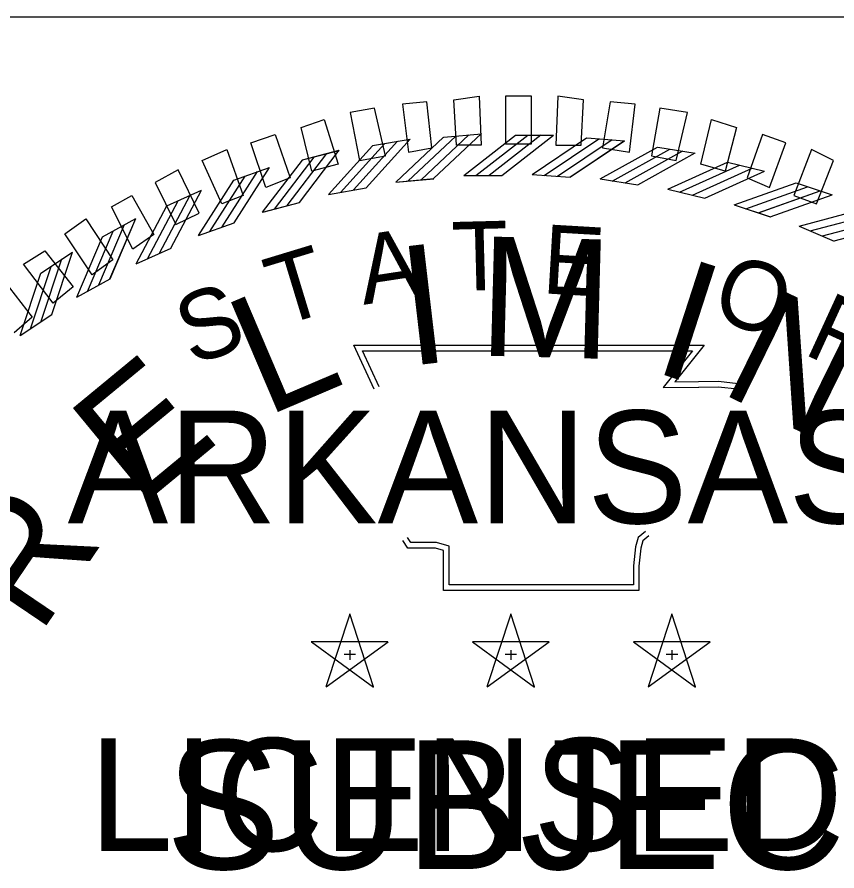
# Model space of a CAD drawing. Extents: x 16 to 1228740, y 11 to 152440.
# Drawn here: x 17.7163 to 17.7977, y 10.9139 to 10.9986 of the extents above; entities that cross this region are included whole.
import ezdxf

# ---------------------------------------------------------------- set-up
doc = ezdxf.new("R2010")
doc.units = 0
for name, color, linetype in [('B_StampERBB', 7, 'Continuous'), ('R_No Plot', 7, 'Continuous'), ('STAMP_FRED', 7, 'Continuous'), ('STAMP_JUSTIN', 7, 'Continuous'), ('STAMP_PRELIM', 7, 'Continuous')]:
    doc.layers.add(name, color=color, linetype=linetype)

msp = doc.modelspace()

# ---------------------------------------------------------------- linework, layer by layer
at = {"layer": 'B_StampERBB'}
for p, q in [((17.751633, 10.985868), (17.755345, 10.986523)), ((17.758689, 10.986711), (17.762443, 10.987057)), ((17.765828, 10.986922), (17.769598, 10.986922)), ((17.77289, 10.986639), (17.776649, 10.986362)), ((17.779937, 10.985724), (17.783661, 10.985138)), ((17.74467, 10.984445), (17.748316, 10.985404)), ((17.786885, 10.98423), (17.790548, 10.983338)), ((17.737849, 10.982452), (17.741403, 10.983709)), ((17.767464, 10.983016), (17.771233, 10.982738)), ((17.753934, 10.982244), (17.757697, 10.982591)), ((17.760683, 10.98291), (17.764462, 10.98291)), ((17.774231, 10.982561), (17.777964, 10.981973)), ((17.793685, 10.982168), (17.797262, 10.980976)), ((17.731215, 10.979903), (17.734654, 10.981449)), ((17.747263, 10.981024), (17.750984, 10.98168)), ((17.780937, 10.981549), (17.784609, 10.980655)), ((17.740715, 10.979257), (17.74437, 10.980218)), ((17.787537, 10.979987), (17.791122, 10.978793)), ((17.724815, 10.976814), (17.728114, 10.978639)), ((17.734336, 10.976955), (17.737898, 10.978215)), ((17.793985, 10.977885), (17.797459, 10.976399)), ((17.718692, 10.973208), (17.721829, 10.975299)), ((17.728168, 10.974134), (17.731615, 10.975684)), ((17.722255, 10.970814), (17.725562, 10.972643)), ((17.716636, 10.967016), (17.71978, 10.969112)), ((17.749354, 10.939355), (17.746995, 10.932119)), ((17.751704, 10.932123), (17.749359, 10.939363)), ((17.765345, 10.939355), (17.762986, 10.932119)), ((17.767695, 10.932123), (17.76535, 10.939363)), ((17.781336, 10.939355), (17.778977, 10.932119)), ((17.783686, 10.932123), (17.781341, 10.939363)), ((17.753156, 10.936593), (17.745545, 10.9366)), ((17.745552, 10.936593), (17.751705, 10.932113)), ((17.747004, 10.932123), (17.753165, 10.936591)), ((17.769147, 10.936593), (17.761536, 10.9366)), ((17.761543, 10.936593), (17.767696, 10.932113)), ((17.762995, 10.932123), (17.769157, 10.936591)), ((17.785138, 10.936593), (17.777527, 10.9366)), ((17.777534, 10.936593), (17.783687, 10.932113)), ((17.778986, 10.932123), (17.785148, 10.936591)), ((17.749361, 10.935783), (17.749361, 10.934828)), ((17.765352, 10.935783), (17.765352, 10.934828)), ((17.781343, 10.935783), (17.781343, 10.934828)), ((17.748812, 10.935377), (17.749943, 10.935377)), ((17.764803, 10.935377), (17.765934, 10.935377)), ((17.780794, 10.935377), (17.781926, 10.935377))]:
    msp.add_line(p, q, dxfattribs=at)
for points in [[(17.749741, 10.981475), (17.754109, 10.986319)], [(17.750979, 10.981682), (17.755348, 10.986526)], [(17.75393, 10.982241), (17.758684, 10.986707)], [(17.755139, 10.982341), (17.759893, 10.986807)], [(17.756441, 10.98249), (17.761195, 10.986956)], [(17.757692, 10.982593), (17.762446, 10.98706)], [(17.760679, 10.982906), (17.765823, 10.986918)], [(17.761892, 10.982895), (17.767036, 10.986907)], [(17.763202, 10.982924), (17.768346, 10.986936)], [(17.764458, 10.982913), (17.769601, 10.986924)], [(17.76746, 10.983012), (17.772884, 10.986636)], [(17.768669, 10.982912), (17.774093, 10.986535)], [(17.769977, 10.982845), (17.775401, 10.986468)], [(17.771229, 10.982741), (17.776653, 10.986365)], [(17.747259, 10.98102), (17.751628, 10.985864)], [(17.748456, 10.98122), (17.752825, 10.986064)], [(17.774226, 10.982558), (17.779931, 10.985721)], [(17.775423, 10.982358), (17.781128, 10.985521)], [(17.741888, 10.97955), (17.745842, 10.984738)], [(17.743147, 10.979911), (17.747101, 10.9851)], [(17.744365, 10.98022), (17.748319, 10.985408)], [(17.776721, 10.982183), (17.782426, 10.985346)], [(17.77796, 10.981977), (17.783665, 10.98514)], [(17.740712, 10.979252), (17.744666, 10.984441)], [(17.780932, 10.981547), (17.786879, 10.984228)], [(17.782108, 10.981249), (17.788055, 10.98393)], [(17.736705, 10.977808), (17.740218, 10.983305)], [(17.737893, 10.978216), (17.741405, 10.983713)], [(17.783387, 10.980967), (17.789334, 10.983648)], [(17.784605, 10.980659), (17.790552, 10.98334)], [(17.734333, 10.97695), (17.737845, 10.982447)], [(17.73548, 10.977344), (17.738993, 10.982841)], [(17.787531, 10.979985), (17.793679, 10.982166)], [(17.73161, 10.975685), (17.734656, 10.981453)], [(17.788679, 10.979591), (17.794827, 10.981772)], [(17.789931, 10.979205), (17.796078, 10.981386)], [(17.729277, 10.974617), (17.732323, 10.980385)], [(17.730459, 10.97518), (17.733506, 10.980948)], [(17.791118, 10.978797), (17.797266, 10.980978)], [(17.728166, 10.974129), (17.731212, 10.979898)], [(17.793979, 10.977884), (17.800286, 10.979549)], [(17.79509, 10.977396), (17.801397, 10.979062)], [(17.724452, 10.972045), (17.727011, 10.978045)], [(17.725556, 10.972643), (17.728116, 10.978643)], [(17.796306, 10.976908), (17.802613, 10.978574)], [(17.797456, 10.976403), (17.803763, 10.978069)], [(17.72332, 10.971386), (17.725879, 10.977386)], [(17.722253, 10.970809), (17.724812, 10.976809)], [(17.719775, 10.969112), (17.72183, 10.975303)], [(17.718724, 10.968425), (17.720779, 10.974616)], [(17.71765, 10.967675), (17.719705, 10.973866)], [(17.716634, 10.967011), (17.718689, 10.973202)], [(17.751782, 10.96169), (17.749773, 10.966041), (17.784542, 10.966062), (17.781637, 10.962412), (17.783999, 10.962442), (17.785972, 10.962468), (17.787944, 10.962253)], [(17.752282, 10.96192), (17.750633, 10.965491), (17.7834, 10.96551), (17.780483, 10.961846), (17.784006, 10.961892), (17.785946, 10.961917), (17.787884, 10.961706)], [(17.778715, 10.947546), (17.777986, 10.946952), (17.777731, 10.946018), (17.777526, 10.944143), (17.777526, 10.94226), (17.759218, 10.94226), (17.759218, 10.944954), (17.759218, 10.946083), (17.757962, 10.946466), (17.755417, 10.946466), (17.755089, 10.946966)], [(17.779063, 10.947119), (17.77847, 10.946636), (17.778273, 10.945915), (17.778077, 10.944113), (17.778077, 10.941709), (17.758667, 10.941709), (17.758667, 10.944954), (17.758667, 10.945675), (17.75788, 10.945915), (17.755119, 10.945915), (17.754629, 10.946664)]]:
    msp.add_lwpolyline(points, dxfattribs=at)
at = {"layer": 'R_No Plot'}
msp.add_line((17.887998, 10.998635), (17.47349, 10.998635), dxfattribs=at)
at = {"layer": 'STAMP_FRED'}
for p, q in [((17.751633, 10.985868), (17.755345, 10.986523)), ((17.758689, 10.986711), (17.762443, 10.987057)), ((17.765828, 10.986922), (17.769598, 10.986922)), ((17.77289, 10.986639), (17.776649, 10.986362)), ((17.779937, 10.985724), (17.783661, 10.985138)), ((17.74467, 10.984445), (17.748316, 10.985404)), ((17.786885, 10.98423), (17.790548, 10.983338)), ((17.737849, 10.982452), (17.741403, 10.983709)), ((17.767464, 10.983016), (17.771233, 10.982738)), ((17.753934, 10.982244), (17.757697, 10.982591)), ((17.760683, 10.98291), (17.764462, 10.98291)), ((17.774231, 10.982561), (17.777964, 10.981973)), ((17.793685, 10.982168), (17.797262, 10.980976)), ((17.731215, 10.979903), (17.734654, 10.981449)), ((17.747263, 10.981024), (17.750984, 10.98168)), ((17.780937, 10.981549), (17.784609, 10.980655)), ((17.740715, 10.979257), (17.74437, 10.980218)), ((17.787537, 10.979987), (17.791122, 10.978793)), ((17.724815, 10.976814), (17.728114, 10.978639)), ((17.734336, 10.976955), (17.737898, 10.978215)), ((17.793985, 10.977885), (17.797459, 10.976399)), ((17.718692, 10.973208), (17.721829, 10.975299)), ((17.728168, 10.974134), (17.731615, 10.975684)), ((17.722255, 10.970814), (17.725562, 10.972643)), ((17.716636, 10.967016), (17.71978, 10.969112)), ((17.749354, 10.939355), (17.746995, 10.932119)), ((17.751704, 10.932123), (17.749359, 10.939363)), ((17.765345, 10.939355), (17.762986, 10.932119)), ((17.767695, 10.932123), (17.76535, 10.939363)), ((17.781336, 10.939355), (17.778977, 10.932119)), ((17.783686, 10.932123), (17.781341, 10.939363)), ((17.753156, 10.936593), (17.745545, 10.9366)), ((17.745552, 10.936593), (17.751705, 10.932113)), ((17.747004, 10.932123), (17.753165, 10.936591)), ((17.769147, 10.936593), (17.761536, 10.9366)), ((17.761543, 10.936593), (17.767696, 10.932113)), ((17.762995, 10.932123), (17.769157, 10.936591)), ((17.785138, 10.936593), (17.777527, 10.9366)), ((17.777534, 10.936593), (17.783687, 10.932113)), ((17.778986, 10.932123), (17.785148, 10.936591)), ((17.749361, 10.935783), (17.749361, 10.934828)), ((17.765352, 10.935783), (17.765352, 10.934828)), ((17.781343, 10.935783), (17.781343, 10.934828)), ((17.748812, 10.935377), (17.749943, 10.935377)), ((17.764803, 10.935377), (17.765934, 10.935377)), ((17.780794, 10.935377), (17.781926, 10.935377))]:
    msp.add_line(p, q, dxfattribs=at)
for points in [[(17.749741, 10.981475), (17.754109, 10.986319)], [(17.750979, 10.981682), (17.755348, 10.986526)], [(17.75393, 10.982241), (17.758684, 10.986707)], [(17.755139, 10.982341), (17.759893, 10.986807)], [(17.756441, 10.98249), (17.761195, 10.986956)], [(17.757692, 10.982593), (17.762446, 10.98706)], [(17.760679, 10.982906), (17.765823, 10.986918)], [(17.761892, 10.982895), (17.767036, 10.986907)], [(17.763202, 10.982924), (17.768346, 10.986936)], [(17.764458, 10.982913), (17.769601, 10.986924)], [(17.76746, 10.983012), (17.772884, 10.986636)], [(17.768669, 10.982912), (17.774093, 10.986535)], [(17.769977, 10.982845), (17.775401, 10.986468)], [(17.771229, 10.982741), (17.776653, 10.986365)], [(17.747259, 10.98102), (17.751628, 10.985864)], [(17.748456, 10.98122), (17.752825, 10.986064)], [(17.774226, 10.982558), (17.779931, 10.985721)], [(17.775423, 10.982358), (17.781128, 10.985521)], [(17.741888, 10.97955), (17.745842, 10.984738)], [(17.743147, 10.979911), (17.747101, 10.9851)], [(17.744365, 10.98022), (17.748319, 10.985408)], [(17.776721, 10.982183), (17.782426, 10.985346)], [(17.77796, 10.981977), (17.783665, 10.98514)], [(17.740712, 10.979252), (17.744666, 10.984441)], [(17.780932, 10.981547), (17.786879, 10.984228)], [(17.782108, 10.981249), (17.788055, 10.98393)], [(17.736705, 10.977808), (17.740218, 10.983305)], [(17.737893, 10.978216), (17.741405, 10.983713)], [(17.783387, 10.980967), (17.789334, 10.983648)], [(17.784605, 10.980659), (17.790552, 10.98334)], [(17.734333, 10.97695), (17.737845, 10.982447)], [(17.73548, 10.977344), (17.738993, 10.982841)], [(17.787531, 10.979985), (17.793679, 10.982166)], [(17.73161, 10.975685), (17.734656, 10.981453)], [(17.788679, 10.979591), (17.794827, 10.981772)], [(17.789931, 10.979205), (17.796078, 10.981386)], [(17.729277, 10.974617), (17.732323, 10.980385)], [(17.730459, 10.97518), (17.733506, 10.980948)], [(17.791118, 10.978797), (17.797266, 10.980978)], [(17.728166, 10.974129), (17.731212, 10.979898)], [(17.793979, 10.977884), (17.800286, 10.979549)], [(17.79509, 10.977396), (17.801397, 10.979062)], [(17.724452, 10.972045), (17.727011, 10.978045)], [(17.725556, 10.972643), (17.728116, 10.978643)], [(17.796306, 10.976908), (17.802613, 10.978574)], [(17.797456, 10.976403), (17.803763, 10.978069)], [(17.72332, 10.971386), (17.725879, 10.977386)], [(17.722253, 10.970809), (17.724812, 10.976809)], [(17.719775, 10.969112), (17.72183, 10.975303)], [(17.718724, 10.968425), (17.720779, 10.974616)], [(17.71765, 10.967675), (17.719705, 10.973866)], [(17.716634, 10.967011), (17.718689, 10.973202)], [(17.751782, 10.96169), (17.749773, 10.966041), (17.784542, 10.966062), (17.781637, 10.962412), (17.783999, 10.962442), (17.785972, 10.962468), (17.787944, 10.962253)], [(17.752282, 10.96192), (17.750633, 10.965491), (17.7834, 10.96551), (17.780483, 10.961846), (17.784006, 10.961892), (17.785946, 10.961917), (17.787884, 10.961706)], [(17.778715, 10.947546), (17.777986, 10.946952), (17.777731, 10.946018), (17.777526, 10.944143), (17.777526, 10.94226), (17.759218, 10.94226), (17.759218, 10.944954), (17.759218, 10.946083), (17.757962, 10.946466), (17.755417, 10.946466), (17.755089, 10.946966)], [(17.779063, 10.947119), (17.77847, 10.946636), (17.778273, 10.945915), (17.778077, 10.944113), (17.778077, 10.941709), (17.758667, 10.941709), (17.758667, 10.944954), (17.758667, 10.945675), (17.75788, 10.945915), (17.755119, 10.945915), (17.754629, 10.946664)]]:
    msp.add_lwpolyline(points, dxfattribs=at)
at = {"layer": 'STAMP_JUSTIN'}
for p, q in [((17.751633, 10.985867), (17.755345, 10.986522)), ((17.758689, 10.98671), (17.762443, 10.987056)), ((17.765828, 10.98692), (17.769598, 10.98692)), ((17.772889, 10.986638), (17.776649, 10.986361)), ((17.779937, 10.985723), (17.783661, 10.985137)), ((17.74467, 10.984444), (17.748316, 10.985403)), ((17.786884, 10.984229), (17.790547, 10.983337)), ((17.737849, 10.982451), (17.741403, 10.983708)), ((17.767464, 10.983015), (17.771233, 10.982737)), ((17.753934, 10.982244), (17.757697, 10.98259)), ((17.760683, 10.982909), (17.764462, 10.982909)), ((17.774231, 10.98256), (17.777963, 10.981972)), ((17.793685, 10.982167), (17.797261, 10.980975)), ((17.731216, 10.979902), (17.734654, 10.981448)), ((17.747263, 10.981023), (17.750984, 10.981679)), ((17.780937, 10.981548), (17.784608, 10.980654)), ((17.740716, 10.979256), (17.74437, 10.980217)), ((17.787536, 10.979986), (17.791121, 10.978792)), ((17.724816, 10.976814), (17.728115, 10.978638)), ((17.734336, 10.976954), (17.737899, 10.978214)), ((17.793984, 10.977884), (17.797458, 10.976398)), ((17.718693, 10.973207), (17.72183, 10.975298)), ((17.728169, 10.974134), (17.731615, 10.975683)), ((17.722256, 10.970813), (17.725562, 10.972642)), ((17.716637, 10.967016), (17.719781, 10.969112)), ((17.749354, 10.939355), (17.746995, 10.932119)), ((17.751704, 10.932123), (17.749359, 10.939363)), ((17.765345, 10.939355), (17.762986, 10.932119)), ((17.767695, 10.932123), (17.76535, 10.939363)), ((17.781336, 10.939355), (17.778977, 10.932119)), ((17.783685, 10.932123), (17.78134, 10.939363)), ((17.753156, 10.936593), (17.745545, 10.9366)), ((17.745552, 10.936593), (17.751705, 10.932114)), ((17.747004, 10.932123), (17.753165, 10.936591)), ((17.769147, 10.936593), (17.761536, 10.9366)), ((17.761543, 10.936593), (17.767696, 10.932114)), ((17.762995, 10.932123), (17.769156, 10.936591)), ((17.785138, 10.936593), (17.777527, 10.9366)), ((17.777534, 10.936593), (17.783686, 10.932114)), ((17.778986, 10.932123), (17.785147, 10.936591)), ((17.749361, 10.935783), (17.749361, 10.934828)), ((17.765352, 10.935783), (17.765352, 10.934828)), ((17.781343, 10.935783), (17.781343, 10.934828)), ((17.748812, 10.935377), (17.749943, 10.935377)), ((17.764803, 10.935377), (17.765934, 10.935377)), ((17.780794, 10.935377), (17.781925, 10.935377))]:
    msp.add_line(p, q, dxfattribs=at)
for points in [[(17.75098, 10.981681), (17.755348, 10.986525)], [(17.75393, 10.98224), (17.758684, 10.986706)], [(17.755139, 10.98234), (17.759893, 10.986806)], [(17.756441, 10.982489), (17.761195, 10.986955)], [(17.757692, 10.982592), (17.762446, 10.987059)], [(17.760679, 10.982905), (17.765822, 10.986917)], [(17.761892, 10.982894), (17.767036, 10.986906)], [(17.763202, 10.982923), (17.768345, 10.986935)], [(17.764457, 10.982912), (17.769601, 10.986923)], [(17.767459, 10.983011), (17.772884, 10.986635)], [(17.768669, 10.982911), (17.774093, 10.986534)], [(17.769977, 10.982844), (17.775401, 10.986467)], [(17.771228, 10.98274), (17.776653, 10.986363)], [(17.747259, 10.981019), (17.751628, 10.985863)], [(17.748456, 10.981219), (17.752825, 10.986063)], [(17.749741, 10.981475), (17.75411, 10.986318)], [(17.774226, 10.982557), (17.779931, 10.98572)], [(17.775423, 10.982357), (17.781127, 10.98552)], [(17.741888, 10.979549), (17.745842, 10.984737)], [(17.743148, 10.97991), (17.747101, 10.985099)], [(17.744365, 10.980219), (17.748319, 10.985407)], [(17.776721, 10.982182), (17.782426, 10.985345)], [(17.777959, 10.981976), (17.783664, 10.985139)], [(17.740712, 10.979251), (17.744666, 10.98444)], [(17.780931, 10.981546), (17.786878, 10.984227)], [(17.782108, 10.981248), (17.788054, 10.983929)], [(17.736706, 10.977807), (17.740218, 10.983304)], [(17.737894, 10.978215), (17.741406, 10.983712)], [(17.783387, 10.980966), (17.789334, 10.983647)], [(17.784604, 10.980658), (17.790551, 10.983339)], [(17.734333, 10.976949), (17.737845, 10.982446)], [(17.735481, 10.977343), (17.738993, 10.98284)], [(17.787531, 10.979984), (17.793678, 10.982165)], [(17.73161, 10.975684), (17.734656, 10.981452)], [(17.788678, 10.97959), (17.794826, 10.981771)], [(17.78993, 10.979204), (17.796078, 10.981385)], [(17.729278, 10.974616), (17.732324, 10.980384)], [(17.73046, 10.975179), (17.733506, 10.980948)], [(17.791118, 10.978796), (17.797265, 10.980977)], [(17.728166, 10.974128), (17.731212, 10.979897)], [(17.793978, 10.977883), (17.800285, 10.979548)], [(17.79509, 10.977395), (17.801396, 10.979061)], [(17.724453, 10.972045), (17.727012, 10.978045)], [(17.725557, 10.972642), (17.728116, 10.978642)], [(17.796305, 10.976907), (17.802612, 10.978573)], [(17.797455, 10.976403), (17.803762, 10.978068)], [(17.723321, 10.971385), (17.72588, 10.977385)], [(17.722254, 10.970808), (17.724813, 10.976808)], [(17.719776, 10.969111), (17.721831, 10.975302)], [(17.718724, 10.968424), (17.72078, 10.974615)], [(17.717651, 10.967674), (17.719706, 10.973865)], [(17.716635, 10.96701), (17.71869, 10.973201)], [(17.751782, 10.961689), (17.749773, 10.966041), (17.784542, 10.966061), (17.781637, 10.962411), (17.783998, 10.962442), (17.785972, 10.962468), (17.787943, 10.962253)], [(17.752282, 10.96192), (17.750633, 10.965491), (17.783399, 10.96551), (17.780483, 10.961846), (17.784005, 10.961891), (17.785945, 10.961917), (17.787883, 10.961705)], [(17.778715, 10.947546), (17.777985, 10.946952), (17.77773, 10.946018), (17.777525, 10.944143), (17.777525, 10.94226), (17.759218, 10.94226), (17.759218, 10.944954), (17.759218, 10.946082), (17.757962, 10.946466), (17.755417, 10.946466), (17.755089, 10.946966)], [(17.779063, 10.947119), (17.77847, 10.946636), (17.778273, 10.945915), (17.778076, 10.944113), (17.778076, 10.941709), (17.758667, 10.941709), (17.758667, 10.944954), (17.758667, 10.945675), (17.75788, 10.945915), (17.755119, 10.945915), (17.754629, 10.946664)]]:
    msp.add_lwpolyline(points, dxfattribs=at)
at = {"layer": 'STAMP_PRELIM'}
for p, q in [((17.75971, 10.990408), (17.76221, 10.990783)), ((17.76221, 10.990783), (17.762402, 10.985908)), ((17.767402, 10.990783), (17.764835, 10.990783)), ((17.764835, 10.990783), (17.764835, 10.986033)), ((17.767402, 10.986033), (17.767402, 10.990783)), ((17.770027, 10.990783), (17.769835, 10.985908)), ((17.772585, 10.990408), (17.770027, 10.990783)), ((17.757027, 10.990224), (17.754585, 10.989974)), ((17.754585, 10.989974), (17.75521, 10.985224)), ((17.757527, 10.985658), (17.757027, 10.990224)), ((17.75996, 10.985908), (17.75971, 10.990408)), ((17.772335, 10.985908), (17.772585, 10.990408)), ((17.77521, 10.990224), (17.77446, 10.985658)), ((17.77771, 10.989974), (17.77521, 10.990224)), ((17.777152, 10.985224), (17.77771, 10.989974)), ((17.751835, 10.989599), (17.749402, 10.989158)), ((17.749402, 10.989158), (17.750335, 10.984408)), ((17.752902, 10.984849), (17.751835, 10.989599)), ((17.780152, 10.989599), (17.779335, 10.984849)), ((17.782902, 10.989158), (17.780152, 10.989599)), ((17.781777, 10.984408), (17.782902, 10.989158)), ((17.744527, 10.987658), (17.746835, 10.988474)), ((17.746835, 10.988474), (17.74821, 10.984033)), ((17.78421, 10.984033), (17.785277, 10.988474)), ((17.785277, 10.988474), (17.787777, 10.987658)), ((17.745585, 10.983349), (17.744527, 10.987658)), ((17.787777, 10.987658), (17.786652, 10.983349)), ((17.739527, 10.986158), (17.74196, 10.986974)), ((17.74196, 10.986974), (17.74346, 10.982658)), ((17.790335, 10.986974), (17.788835, 10.982658)), ((17.792652, 10.986158), (17.790335, 10.986974)), ((17.73471, 10.984408), (17.737152, 10.985474)), ((17.737152, 10.985474), (17.738777, 10.980908)), ((17.741027, 10.981724), (17.739527, 10.986158)), ((17.75521, 10.985224), (17.757527, 10.985658)), ((17.762402, 10.985908), (17.75996, 10.985908)), ((17.764835, 10.986033), (17.767402, 10.986033)), ((17.769835, 10.985908), (17.772335, 10.985908)), ((17.77446, 10.985658), (17.777152, 10.985224)), ((17.791027, 10.981724), (17.792652, 10.986158)), ((17.79521, 10.985474), (17.79346, 10.980908)), ((17.797402, 10.984408), (17.79521, 10.985474)), ((17.750335, 10.984408), (17.752902, 10.984849)), ((17.779335, 10.984849), (17.781777, 10.984408)), ((17.736652, 10.980099), (17.73471, 10.984408)), ((17.74821, 10.984033), (17.745585, 10.983349)), ((17.786652, 10.983349), (17.78421, 10.984033)), ((17.79571, 10.980099), (17.797402, 10.984408)), ((17.732335, 10.983474), (17.730027, 10.982224)), ((17.734402, 10.979158), (17.732335, 10.983474)), ((17.730027, 10.982224), (17.732085, 10.978033)), ((17.74346, 10.982658), (17.741027, 10.981724)), ((17.788835, 10.982658), (17.791027, 10.981724)), ((17.72571, 10.979783), (17.72771, 10.980908)), ((17.72771, 10.980908), (17.729902, 10.977033)), ((17.738777, 10.980908), (17.736652, 10.980099)), ((17.79346, 10.980908), (17.79571, 10.980099)), ((17.727835, 10.975599), (17.72571, 10.979783)), ((17.732085, 10.978033), (17.734402, 10.979158)), ((17.721085, 10.977099), (17.723152, 10.978599)), ((17.723152, 10.978599), (17.725835, 10.974533)), ((17.723777, 10.973033), (17.721085, 10.977099)), ((17.729902, 10.977033), (17.727835, 10.975599)), ((17.71696, 10.974099), (17.719085, 10.975408)), ((17.719085, 10.975408), (17.721902, 10.971849)), ((17.725835, 10.974533), (17.723777, 10.973033)), ((17.719902, 10.970224), (17.71696, 10.974099)), ((17.715027, 10.972474), (17.717835, 10.968849)), ((17.721902, 10.971849), (17.719902, 10.970224)), ((17.717835, 10.968849), (17.716027, 10.967283))]:
    msp.add_line(p, q, dxfattribs=at)

# ---------------------------------------------------------------- texts
at = {"layer": 'B_StampERBB'}
for s, rotation, p in [('T', 1.47887, (17.759579, 10.971424)), ('E', 356.67203, (17.768356, 10.971216)), ('A', 8.67877, (17.750722, 10.97006)), ('T', 16.90148, (17.742394, 10.967886)), ('O', 341.2218, (17.78501, 10.968864)), ('S', 19.77256, (17.733673, 10.96397)), ('F', 335.36282, (17.794253, 10.96525))]:
    msp.add_text(s, height=0.006859, rotation=rotation, dxfattribs=at).set_placement(p)
for s, p in [('ARKANSAS', (17.72135, 10.948369)), ('LICENSED', (17.723482, 10.915834))]:
    msp.add_text(s, height=0.0111938, dxfattribs=at).set_placement(p)
at = {"layer": 'STAMP_FRED'}
for s, rotation, p in [('T', 1.47887, (17.759579, 10.971424)), ('E', 356.67203, (17.768356, 10.971216)), ('A', 8.67877, (17.750722, 10.97006)), ('T', 16.90148, (17.742394, 10.967886)), ('O', 341.2218, (17.78501, 10.968864)), ('S', 19.77256, (17.733673, 10.96397)), ('F', 335.36282, (17.794253, 10.96525))]:
    msp.add_text(s, height=0.006859, rotation=rotation, dxfattribs=at).set_placement(p)
for s, p in [('ARKANSAS', (17.72135, 10.948369)), ('LICENSED', (17.723482, 10.915834))]:
    msp.add_text(s, height=0.0111938, dxfattribs=at).set_placement(p)
at = {"layer": 'STAMP_JUSTIN'}
for s, rotation, p in [('T', 1.47887, (17.759579, 10.971424)), ('E', 356.67203, (17.768356, 10.971216)), ('A', 8.67877, (17.750722, 10.970059)), ('T', 16.90148, (17.742395, 10.967885)), ('O', 341.2218, (17.785009, 10.968864)), ('S', 19.77256, (17.733674, 10.96397)), ('F', 335.36282, (17.794252, 10.965249))]:
    msp.add_text(s, height=0.006859, rotation=rotation, dxfattribs=at).set_placement(p)
for s, p in [('ARKANSAS', (17.721351, 10.948369)), ('LICENSED', (17.723483, 10.915835))]:
    msp.add_text(s, height=0.0111936, dxfattribs=at).set_placement(p)
at = {"layer": 'STAMP_PRELIM'}
for s, rotation, p in [('M', 358.46666, (17.762085, 10.965033)), ('I', 6.67523, (17.755152, 10.963974)), ('I', 342.04953, (17.77921, 10.963533)), ('N', 333.84096, (17.785902, 10.961474)), ('L', 23.09236, (17.741027, 10.958908)), ('E', 39.5095, (17.728402, 10.949849)), ('R', 55.92663, (17.718527, 10.937158))]:
    msp.add_text(s, height=0.011841, rotation=rotation, dxfattribs=at).set_placement(p)
msp.add_text('SUBJECT', height=0.0127938, dxfattribs=at).set_placement((17.731085, 10.914033))

doc.saveas('drawing.dxf')
